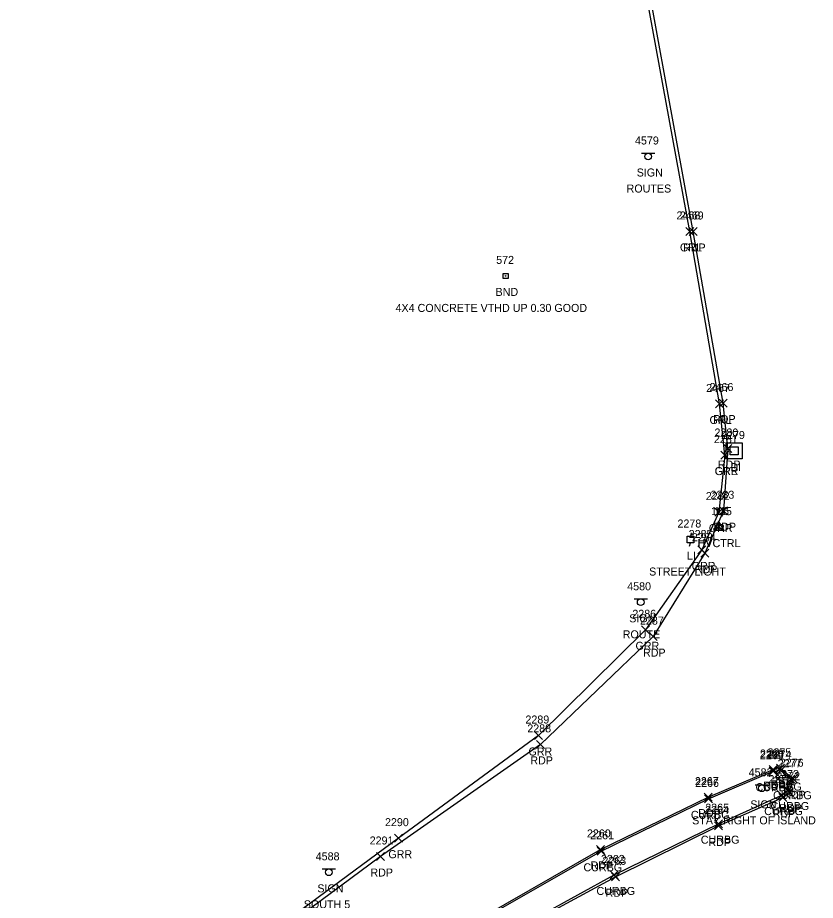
# Model space of a CAD drawing. Extents: x 1690689 to 1696275, y 438760 to 444007.
# Drawn here: x 1691172.8 to 1691372.1, y 440321.4 to 440542 of the extents above; entities that cross this region are included whole.
import ezdxf

# ---------------------------------------------------------------- set-up
doc = ezdxf.new("R2010")
doc.units = 0
for name, color, linetype in [('C_A', 7, 'Continuous'), ('C_I', 7, 'Continuous'), ('CPSM', 7, 'Continuous'), ('D_A', 7, 'Continuous'), ('D_I', 7, 'Continuous'), ('DS', 7, 'Continuous'), ('Level 18', 7, 'Continuous'), ('M_A', 7, 'Continuous'), ('M_C', 7, 'Continuous'), ('M_I', 7, 'Continuous'), ('P_A', 7, 'Continuous'), ('P_I', 7, 'Continuous'), ('P_TIC', 7, 'Continuous'), ('PET', 7, 'Continuous'), ('R_A', 7, 'Continuous'), ('R_I', 7, 'Continuous'), ('R_TIC', 7, 'Continuous'), ('RC', 7, 'Continuous'), ('RGR', 7, 'Continuous'), ('S_A', 7, 'Continuous'), ('S_C', 7, 'Continuous'), ('S_I', 7, 'Continuous'), ('SSGN', 7, 'Continuous'), ('U_A', 7, 'Continuous'), ('U_C', 7, 'Continuous'), ('U_I', 7, 'Continuous'), ('ULP', 7, 'Continuous')]:
    doc.layers.add(name, color=color, linetype=linetype)

msp = doc.modelspace()

# ---------------------------------------------------------------- linework, layer by layer
at = {"layer": 'CPSM'}
for p, q in [((1691346.72, 440413.95), (1691347.97, 440416.11)), ((1691346.74, 440413.93), (1691347.99, 440416.1)), ((1691349.22, 440413.95), (1691347.97, 440416.11)), ((1691347.97, 440414.67), (1691347.97, 440416.11)), ((1691349.24, 440413.93), (1691347.99, 440416.1)), ((1691348, 440414.66), (1691347.99, 440416.1)), ((1691346.72, 440413.95), (1691347.97, 440414.67)), ((1691346.72, 440413.95), (1691349.22, 440413.95)), ((1691346.74, 440413.93), (1691348, 440414.66)), ((1691346.74, 440413.93), (1691349.24, 440413.93)), ((1691347.97, 440414.67), (1691347.97, 440414.67)), ((1691347.97, 440414.67), (1691349.22, 440413.95)), ((1691348, 440414.66), (1691348, 440414.66)), ((1691348, 440414.66), (1691349.24, 440413.93))]:
    msp.add_line(p, q, dxfattribs=at)
at = {"layer": 'DS'}
for p, q in [((1691349.78, 440435.69), (1691353.78, 440435.69)), ((1691349.78, 440431.69), (1691349.78, 440435.69)), ((1691353.78, 440435.69), (1691353.78, 440431.69)), ((1691350.78, 440432.69), (1691350.78, 440434.69)), ((1691350.78, 440434.69), (1691352.78, 440434.69)), ((1691351.79, 440433.69), (1691351.79, 440433.69)), ((1691351.79, 440433.69), (1691351.79, 440433.69)), ((1691352.78, 440434.69), (1691352.78, 440432.69)), ((1691353.78, 440431.69), (1691349.78, 440431.69)), ((1691352.78, 440432.69), (1691350.78, 440432.69))]:
    msp.add_line(p, q, dxfattribs=at)
at = {"layer": 'Level 18'}
msp.add_lwpolyline([(1691294.07, 440478.06), (1691295.32, 440478.06), (1691295.32, 440476.81), (1691294.07, 440476.81)], close=True, dxfattribs=at)
msp.add_circle((1691294.69, 440477.44), 0.0833, dxfattribs=at)
at = {"layer": 'P_TIC'}
for points in [[(1691340.53, 440487.54), (1691342.53, 440489.54)], [(1691342.53, 440487.54), (1691340.53, 440489.54)], [(1691348.02, 440444.67), (1691350.02, 440446.67)], [(1691350.02, 440444.67), (1691348.02, 440446.67)], [(1691349.23, 440433.31), (1691351.23, 440435.31)], [(1691351.23, 440433.31), (1691349.23, 440435.31)], [(1691349.23, 440433.31), (1691351.23, 440435.31)], [(1691351.23, 440433.31), (1691349.23, 440435.31)], [(1691348.14, 440417.76), (1691350.14, 440419.76)], [(1691350.14, 440417.76), (1691348.14, 440419.76)], [(1691343.48, 440407.13), (1691345.48, 440409.13)], [(1691345.48, 440407.13), (1691343.48, 440409.13)], [(1691330.52, 440386.3), (1691332.52, 440388.3)], [(1691332.52, 440386.3), (1691330.52, 440388.3)], [(1691302.37, 440359.38), (1691304.37, 440361.38)], [(1691304.37, 440359.38), (1691302.37, 440361.38)], [(1691360.53, 440353.09), (1691362.53, 440355.09)], [(1691362.53, 440353.09), (1691360.53, 440355.09)], [(1691362.38, 440353.4), (1691364.38, 440355.4)], [(1691364.38, 440353.4), (1691362.38, 440355.4)], [(1691365.51, 440350.8), (1691367.51, 440352.8)], [(1691367.51, 440350.8), (1691365.51, 440352.8)], [(1691365.51, 440350.8), (1691367.51, 440352.8)], [(1691367.51, 440350.8), (1691365.51, 440352.8)], [(1691344.3, 440346.19), (1691346.3, 440348.19)], [(1691346.3, 440346.19), (1691344.3, 440348.19)], [(1691362.97, 440346.12), (1691364.97, 440348.12)], [(1691364.97, 440346.12), (1691362.97, 440348.12)], [(1691364.58, 440347.43), (1691366.58, 440349.43)], [(1691366.58, 440347.43), (1691364.58, 440349.43)], [(1691346.86, 440338.99), (1691348.86, 440340.99)], [(1691348.86, 440338.99), (1691346.86, 440340.99)], [(1691317.39, 440333.13), (1691319.39, 440335.13)], [(1691319.39, 440333.13), (1691317.39, 440335.13)], [(1691262.42, 440331.36), (1691264.42, 440333.36)], [(1691264.42, 440331.36), (1691262.42, 440333.36)], [(1691321.18, 440326.29), (1691323.18, 440328.29)], [(1691323.18, 440326.29), (1691321.18, 440328.29)]]:
    msp.add_lwpolyline(points, dxfattribs=at)
at = {"layer": 'PET'}
for points in [[(1691350.23, 440434.31), (1691349.02, 440445.67), (1691341.53, 440488.54), (1691328.03, 440562.61), (1691315.34, 440632.97), (1691299.08, 440720.53), (1691280.68, 440820.26), (1691274.23, 440854.76)], [(1691350.23, 440434.31), (1691349.14, 440418.76), (1691344.48, 440408.13), (1691331.52, 440387.3), (1691303.37, 440360.38), (1691263.42, 440332.36), (1691228.62, 440306.53), (1691195.29, 440277.6), (1691167.18, 440250.73), (1691141.5, 440223.7), (1691112.67, 440190.9), (1691079.93, 440151.15), (1691042.34, 440096.86), (1691025.68, 440069.53), (1690997.76, 440016.99), (1690974.62, 439962.54), (1690941.25, 439874.63), (1690911.15, 439796.35), (1690882.73, 439722.65), (1690849.69, 439636.1), (1690819.8, 439560.64), (1690802.57, 439520.92), (1690786.15, 439486.46), (1690768.52, 439453.49)], [(1691225.02, 440272.1), (1691225.43, 440273.46), (1691252.85, 440293.96), (1691282.68, 440313.59), (1691318.39, 440334.13), (1691345.3, 440347.19), (1691361.53, 440354.09), (1691363.38, 440354.4), (1691366.51, 440351.8)], [(1691225.02, 440272.1), (1691226.61, 440271.82), (1691255.75, 440289.84), (1691285.69, 440307.52), (1691322.18, 440327.29), (1691347.86, 440339.99), (1691363.97, 440347.12), (1691365.58, 440348.43), (1691366.51, 440351.8)]]:
    msp.add_lwpolyline(points, dxfattribs=at)
at = {"layer": 'R_TIC'}
for points in [[(1691339.7, 440487.56), (1691341.7, 440489.56)], [(1691341.7, 440487.56), (1691339.7, 440489.56)], [(1691347.1, 440444.44), (1691349.1, 440446.44)], [(1691349.1, 440444.44), (1691347.1, 440446.44)], [(1691348.43, 440431.67), (1691350.43, 440433.67)], [(1691350.43, 440431.67), (1691348.43, 440433.67)], [(1691348.43, 440431.67), (1691350.43, 440433.67)], [(1691350.43, 440431.67), (1691348.43, 440433.67)], [(1691346.98, 440417.43), (1691348.98, 440419.43)], [(1691348.98, 440417.43), (1691346.98, 440419.43)], [(1691342.69, 440407.96), (1691344.69, 440409.96)], [(1691344.69, 440407.96), (1691342.69, 440409.96)], [(1691328.67, 440388.01), (1691330.67, 440390.01)], [(1691330.67, 440388.01), (1691328.67, 440390.01)], [(1691301.91, 440361.59), (1691303.91, 440363.59)], [(1691303.91, 440361.59), (1691301.91, 440363.59)], [(1691360.55, 440352.68), (1691362.55, 440354.68)], [(1691362.55, 440352.68), (1691360.55, 440354.68)], [(1691362.43, 440352.84), (1691364.43, 440354.84)], [(1691364.43, 440352.84), (1691362.43, 440354.84)], [(1691364.94, 440350.67), (1691366.94, 440352.67)], [(1691366.94, 440350.67), (1691364.94, 440352.67)], [(1691364.94, 440350.67), (1691366.94, 440352.67)], [(1691366.94, 440350.67), (1691364.94, 440352.67)], [(1691364.3, 440347.97), (1691366.3, 440349.97)], [(1691366.3, 440347.97), (1691364.3, 440349.97)], [(1691344.41, 440345.76), (1691346.41, 440347.76)], [(1691346.41, 440345.76), (1691344.41, 440347.76)], [(1691362.72, 440346.71), (1691364.72, 440348.71)], [(1691364.72, 440346.71), (1691362.72, 440348.71)], [(1691346.88, 440339.56), (1691348.88, 440341.56)], [(1691348.88, 440339.56), (1691346.88, 440341.56)], [(1691266.89, 440335.94), (1691268.89, 440337.94)], [(1691268.89, 440335.94), (1691266.89, 440337.94)], [(1691317.57, 440332.66), (1691319.57, 440334.66)], [(1691319.57, 440332.66), (1691317.57, 440334.66)], [(1691320.81, 440326.75), (1691322.81, 440328.75)], [(1691322.81, 440326.75), (1691320.81, 440328.75)]]:
    msp.add_lwpolyline(points, dxfattribs=at)
at = {"layer": 'RC'}
for points in [[(1691225.6, 440272.27), (1691225.61, 440273.36), (1691253.24, 440293.61), (1691282.84, 440313.25), (1691318.57, 440333.66), (1691345.41, 440346.76), (1691361.55, 440353.68), (1691363.43, 440353.84), (1691365.94, 440351.67)], [(1691225.6, 440272.27), (1691226.34, 440272.22), (1691255.58, 440290.16), (1691285.48, 440307.78), (1691321.81, 440327.75), (1691347.88, 440340.56), (1691363.72, 440347.71), (1691365.3, 440348.97), (1691365.94, 440351.67)]]:
    msp.add_lwpolyline(points, dxfattribs=at)
at = {"layer": 'RGR'}
for points in [[(1691349.43, 440432.67), (1691348.1, 440445.44), (1691340.7, 440488.56), (1691327.21, 440562.16), (1691314.3, 440632.73), (1691298.42, 440720.43), (1691280.26, 440820.33), (1691273.69, 440854.21)], [(1691349.43, 440432.67), (1691347.98, 440418.43), (1691343.69, 440408.96), (1691329.67, 440389.01), (1691302.91, 440362.59), (1691267.89, 440336.94), (1691227.82, 440307.25), (1691194.83, 440278.1), (1691167.11, 440252.31), (1691141.57, 440225.08), (1691111.98, 440191.23), (1691079.38, 440151.78), (1691041.5, 440096.83), (1691025.25, 440070.41), (1690997.2, 440017.23), (1690973.8, 439963.26), (1690940.62, 439875.02), (1690910.96, 439797.66), (1690882.27, 439722.91), (1690848.92, 439636.2), (1690819.28, 439560.62), (1690801.86, 439521.17), (1690785.27, 439486.93), (1690767.83, 439453.78)]]:
    msp.add_lwpolyline(points, dxfattribs=at)
at = {"layer": 'SSGN'}
for p, q in [((1691328.66, 440508.13), (1691331.99, 440508.13)), ((1691330.31, 440507.3), (1691330.31, 440507.3)), ((1691326.79, 440396.74), (1691330.12, 440396.74)), ((1691328.44, 440395.9), (1691328.44, 440395.9)), ((1691357.05, 440350.24), (1691360.38, 440350.24)), ((1691358.7, 440349.41), (1691358.7, 440349.41)), ((1691248.87, 440329.26), (1691252.2, 440329.26)), ((1691250.51, 440328.42), (1691250.51, 440328.42))]:
    msp.add_line(p, q, dxfattribs=at)
for centre in [(1691330.31, 440507.3), (1691328.44, 440395.9), (1691358.7, 440349.41), (1691250.51, 440328.42)]:
    msp.add_circle(centre, 0.833, dxfattribs=at)
at = {"layer": 'ULP'}
for p, q in [((1691340.05, 440410.74), (1691340.05, 440412.41)), ((1691340.05, 440412.41), (1691341.72, 440412.41)), ((1691341.05, 440413.24), (1691340.89, 440412.41)), ((1691340.89, 440411.57), (1691340.89, 440411.57)), ((1691341.72, 440412.41), (1691341.72, 440410.74)), ((1691341.72, 440410.74), (1691340.05, 440410.74)), ((1691340.64, 440409.91), (1691340.89, 440410.74))]:
    msp.add_line(p, q, dxfattribs=at)

# ---------------------------------------------------------------- texts
at = {"layer": 'C_A'}
for p in [(1691342.66, 440409.67), (1691342.69, 440409.66)]:
    msp.add_text('HVCTRL', height=2, dxfattribs=at).set_placement(p)
at = {"layer": 'C_I'}
for s, p in [('106', (1691346.04, 440417.67)), ('115', (1691346.77, 440417.66))]:
    msp.add_text(s, height=2, dxfattribs=at).set_placement(p)
at = {"layer": 'D_A'}
msp.add_text('DI', height=2, dxfattribs=at).set_placement((1691350.84, 440428.69))
at = {"layer": 'D_I'}
msp.add_text('2279', height=2, dxfattribs=at).set_placement((1691348.52, 440436.69))
at = {"layer": 'M_A'}
msp.add_text('BND', height=2, dxfattribs=at).set_placement((1691292.18, 440472.44))
at = {"layer": 'M_C'}
msp.add_text('4X4 CONCRETE VTHD UP 0.30 GOOD', height=2, dxfattribs=at).set_placement((1691267.19, 440468.44))
at = {"layer": 'M_I'}
msp.add_text('572', height=2, dxfattribs=at).set_placement((1691292.33, 440480.44))
at = {"layer": 'P_A'}
for p in [(1691339.02, 440483.54), (1691346.51, 440440.67), (1691347.72, 440429.31), (1691347.72, 440429.31), (1691346.63, 440413.76), (1691341.96, 440403.13), (1691329.01, 440382.3), (1691300.86, 440355.38), (1691359.02, 440349.09), (1691360.87, 440349.4), (1691364, 440346.8), (1691364, 440346.8), (1691363.07, 440343.43), (1691342.79, 440342.19), (1691361.45, 440342.12), (1691345.35, 440334.99), (1691315.88, 440329.13), (1691260.9, 440327.36), (1691319.67, 440322.29)]:
    msp.add_text('RDP', height=2, dxfattribs=at).set_placement(p)
at = {"layer": 'P_I'}
for s, p in [('2469', (1691338.22, 440491.54)), ('2466', (1691345.66, 440448.67)), ('2280', (1691346.88, 440437.31)), ('2280', (1691346.88, 440437.31)), ('2283', (1691345.88, 440421.76)), ('2284', (1691341.22, 440411.13)), ('2287', (1691328.26, 440390.3)), ('2288', (1691300.11, 440363.38)), ('2268', (1691358.23, 440357.09)), ('2275', (1691360.12, 440357.4)), ('2276', (1691363.2, 440354.8)), ('2276', (1691363.2, 440354.8)), ('2267', (1691341.99, 440350.19)), ('2271', (1691361.27, 440350.12)), ('2272', (1691362.32, 440351.43)), ('2264', (1691344.55, 440342.99)), ('2260', (1691315, 440337.13)), ('2291', (1691260.72, 440335.36)), ('2263', (1691318.87, 440330.29))]:
    msp.add_text(s, height=2, dxfattribs=at).set_placement(p)
at = {"layer": 'R_A'}
for s, p in [('GRL', (1691338.24, 440483.56)), ('GRL', (1691345.64, 440440.44)), ('GRR', (1691346.92, 440427.67)), ('GRL', (1691346.97, 440427.67)), ('GRR', (1691345.47, 440413.43)), ('GRR', (1691341.18, 440403.96)), ('GRR', (1691327.15, 440384.01)), ('GRR', (1691300.4, 440357.59)), ('CURBG', (1691357.14, 440348.68)), ('CURBG', (1691359.01, 440348.84)), ('CURBG', (1691361.52, 440346.67)), ('CURBG', (1691361.52, 440346.67)), ('CURBG', (1691360.88, 440343.97)), ('CURBG', (1691340.99, 440341.76)), ('CURBG', (1691359.3, 440342.71)), ('CURBG', (1691343.46, 440335.56)), ('GRR', (1691265.38, 440331.94)), ('CURBG', (1691314.15, 440328.66)), ('CURBG', (1691317.39, 440322.75))]:
    msp.add_text(s, height=2, dxfattribs=at).set_placement(p)
at = {"layer": 'R_I'}
for s, p in [('2468', (1691337.39, 440491.56)), ('2467', (1691344.79, 440448.44)), ('2281', (1691346.73, 440435.67)), ('2281', (1691346.73, 440435.67)), ('2282', (1691344.72, 440421.43)), ('2285', (1691340.43, 440411.96)), ('2286', (1691326.35, 440392.01)), ('2289', (1691299.64, 440365.59)), ('2269', (1691358.24, 440356.68)), ('2274', (1691360.17, 440356.84)), ('2277', (1691362.68, 440354.67)), ('2277', (1691362.68, 440354.67)), ('2273', (1691362.04, 440351.97)), ('2266', (1691342.05, 440349.76)), ('2270', (1691360.37, 440350.71)), ('2265', (1691344.57, 440343.56)), ('2290', (1691264.55, 440339.94)), ('2261', (1691315.83, 440336.66)), ('2262', (1691318.5, 440330.75))]:
    msp.add_text(s, height=2, dxfattribs=at).set_placement(p)
at = {"layer": 'S_A'}
for p in [(1691327.44, 440502.28), (1691325.58, 440390.88), (1691355.84, 440344.39), (1691247.65, 440323.4)]:
    msp.add_text('SIGN', height=2, dxfattribs=at).set_placement(p)
at = {"layer": 'S_C'}
for s, p in [('ROUTES', (1691324.92, 440498.28)), ('ROUTE', (1691323.95, 440386.88)), ('STAY RIGHT OF ISLAND', (1691341.3, 440340.39)), ('SOUTH 5', (1691244.27, 440319.4))]:
    msp.add_text(s, height=2, dxfattribs=at).set_placement(p)
at = {"layer": 'S_I'}
for s, p in [('4579', (1691327.02, 440510.28)), ('4580', (1691325.07, 440398.88)), ('4582', (1691355.42, 440352.39)), ('4588', (1691247.24, 440331.4))]:
    msp.add_text(s, height=2, dxfattribs=at).set_placement(p)
at = {"layer": 'U_A'}
msp.add_text('LI', height=2, dxfattribs=at).set_placement((1691339.99, 440406.57))
at = {"layer": 'U_C'}
msp.add_text('STREET LIGHT', height=2, dxfattribs=at).set_placement((1691330.55, 440402.57))
at = {"layer": 'U_I'}
msp.add_text('2278', height=2, dxfattribs=at).set_placement((1691337.63, 440414.57))

doc.saveas('drawing.dxf')
